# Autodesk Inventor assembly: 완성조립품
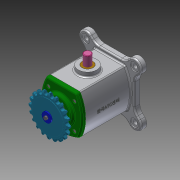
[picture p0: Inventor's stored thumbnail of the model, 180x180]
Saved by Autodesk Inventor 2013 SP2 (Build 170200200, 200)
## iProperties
Created: 2022-01
Part Number: 완성조립품
Document SubType Name: Assembly
Designer: aa
Author: aa
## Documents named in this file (13)
- C:\Users\aa\Desktop\720106V1022\완성조립품.iam
- C:\Users\aa\Desktop\720106V1022\본체.ipt
- C:\Users\aa\Desktop\720106V1022\베어링 6203.ipt
- C:\Users\aa\Desktop\720106V1022\볼트 M4 x 12.ipt
- C:\Users\aa\Desktop\720106V1022\부시.ipt
- C:\Users\aa\Desktop\720106V1022\스프로킷.ipt
- C:\Users\aa\Desktop\720106V1022\슬라이더.ipt
- C:\Users\aa\Desktop\720106V1022\오일 실 17 x 30 x 8.ipt
- C:\Users\aa\Desktop\720106V1022\와셔 4 x 20.ipt
- C:\Users\aa\Desktop\720106V1022\육각머리볼트 M4.ipt
- C:\Users\aa\Desktop\720106V1022\커버.ipt
- C:\Users\aa\Desktop\720106V1022\키 5 x 5.ipt
- C:\Users\aa\Desktop\720106V1022\편심축.ipt
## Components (1 placed, 1 different names)
1. M4x0.7x12:1
